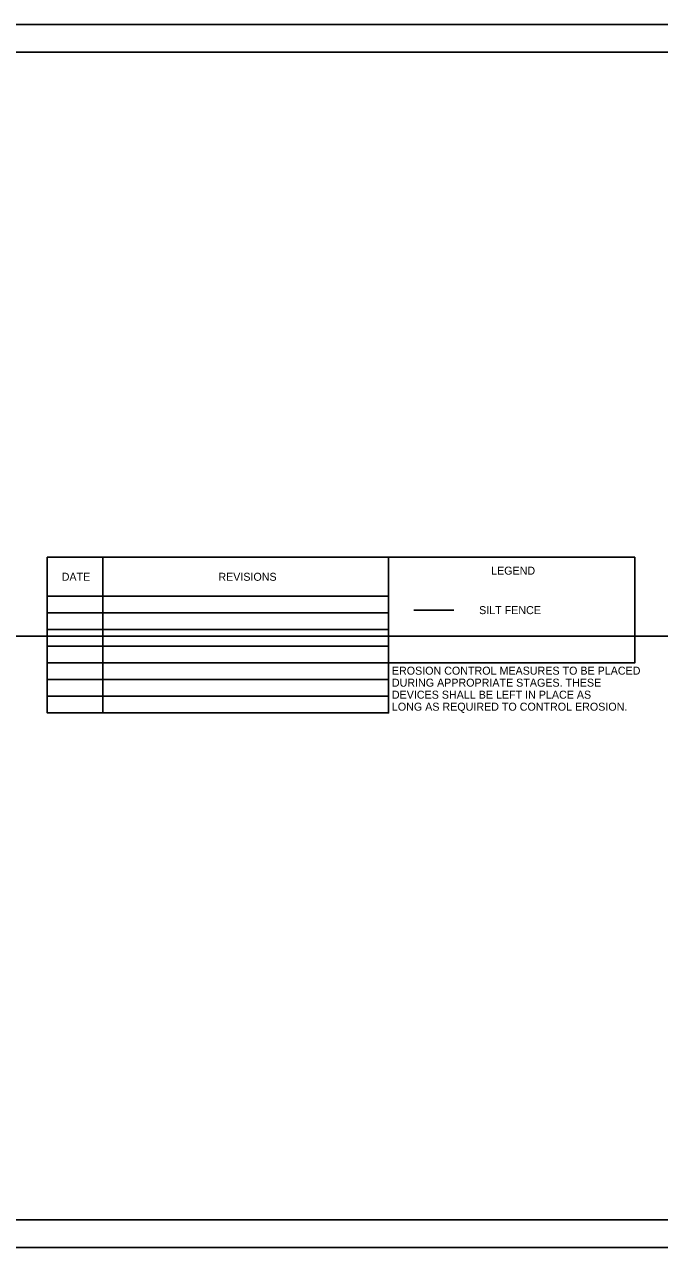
# Model space of a CAD drawing. Extents: x -0.29 to 1.42, y 0 to 0.92.
# Drawn here: x 0.47 to 0.947, y 0 to 0.917 of the extents above; entities that cross this region are included whole.
import ezdxf

# ---------------------------------------------------------------- set-up
doc = ezdxf.new("R2010")
doc.units = 0
for name, color, linetype in [('Default', 7, 'Continuous'), ('DSN_DRFT_Guideline-No-Plot', 7, 'Continuous'), ('MOD_CMP_ACHM Base Course', 7, 'Continuous'), ('SHET_Border-Lines', 7, 'Continuous')]:
    doc.layers.add(name, color=color, linetype=linetype)

msp = doc.modelspace()

# ---------------------------------------------------------------- linework, layer by layer
at = {"layer": 'Default'}
for p, q in [((0.52922, 0.5173), (0.52922, 0.40063)), ((0.48755, 0.48813), (0.7434, 0.48813)), ((0.7624, 0.47772), (0.7924, 0.47772)), ((0.48755, 0.47563), (0.7434, 0.47563)), ((0.48755, 0.46313), (0.7434, 0.46313)), ((0.48755, 0.45063), (0.7434, 0.45063)), ((0.48755, 0.43813), (0.7434, 0.43813)), ((0.48755, 0.42563), (0.7434, 0.42563)), ((0.48755, 0.41313), (0.7434, 0.41313))]:
    msp.add_line(p, q, dxfattribs=at)
for points in [[(0.48755, 0.5173), (0.7434, 0.5173), (0.7434, 0.40063), (0.48755, 0.40063)], [(0.7434, 0.5173), (0.92798, 0.5173), (0.92798, 0.43813), (0.7434, 0.43813)]]:
    msp.add_lwpolyline(points, close=True, dxfattribs=at)
at = {"layer": 'DSN_DRFT_Guideline-No-Plot'}
msp.add_lwpolyline([(0, 0), (1.41667, 0), (1.41667, 0.91667), (0, 0.91667)], close=True, dxfattribs=at)
at = {"layer": 'MOD_CMP_ACHM Base Course'}
msp.add_line((0.48755, 0.40063), (0.7434, 0.40063), dxfattribs=at)
at = {"layer": 'SHET_Border-Lines'}
msp.add_line((0.02083, 0.45833), (1.39583, 0.45833), dxfattribs=at)
msp.add_lwpolyline([(0.02083, 0.02083), (1.39583, 0.02083), (1.39583, 0.89583), (0.02083, 0.89583)], close=True, dxfattribs=at)

# ---------------------------------------------------------------- texts
at = {"layer": 'Default'}
for s, p in [('DATE', (0.49837, 0.49972)), ('REVISIONS', (0.61581, 0.49972)), ('LEGEND', (0.82028, 0.5043)), ('SILT FENCE', (0.81131, 0.47472)), ('EROSION CONTROL MEASURES TO BE PLACED', (0.7459, 0.42935)), ('DURING APPROPRIATE STAGES. THESE ', (0.7459, 0.42035)), ('DEVICES SHALL BE LEFT IN PLACE AS ', (0.7459, 0.41135)), ('LONG AS REQUIRED TO CONTROL EROSION.', (0.7459, 0.40235))]:
    msp.add_text(s, height=0.006, dxfattribs=at).set_placement(p)

doc.saveas('drawing.dxf')
